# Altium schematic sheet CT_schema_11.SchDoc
size 741 x 377 mm
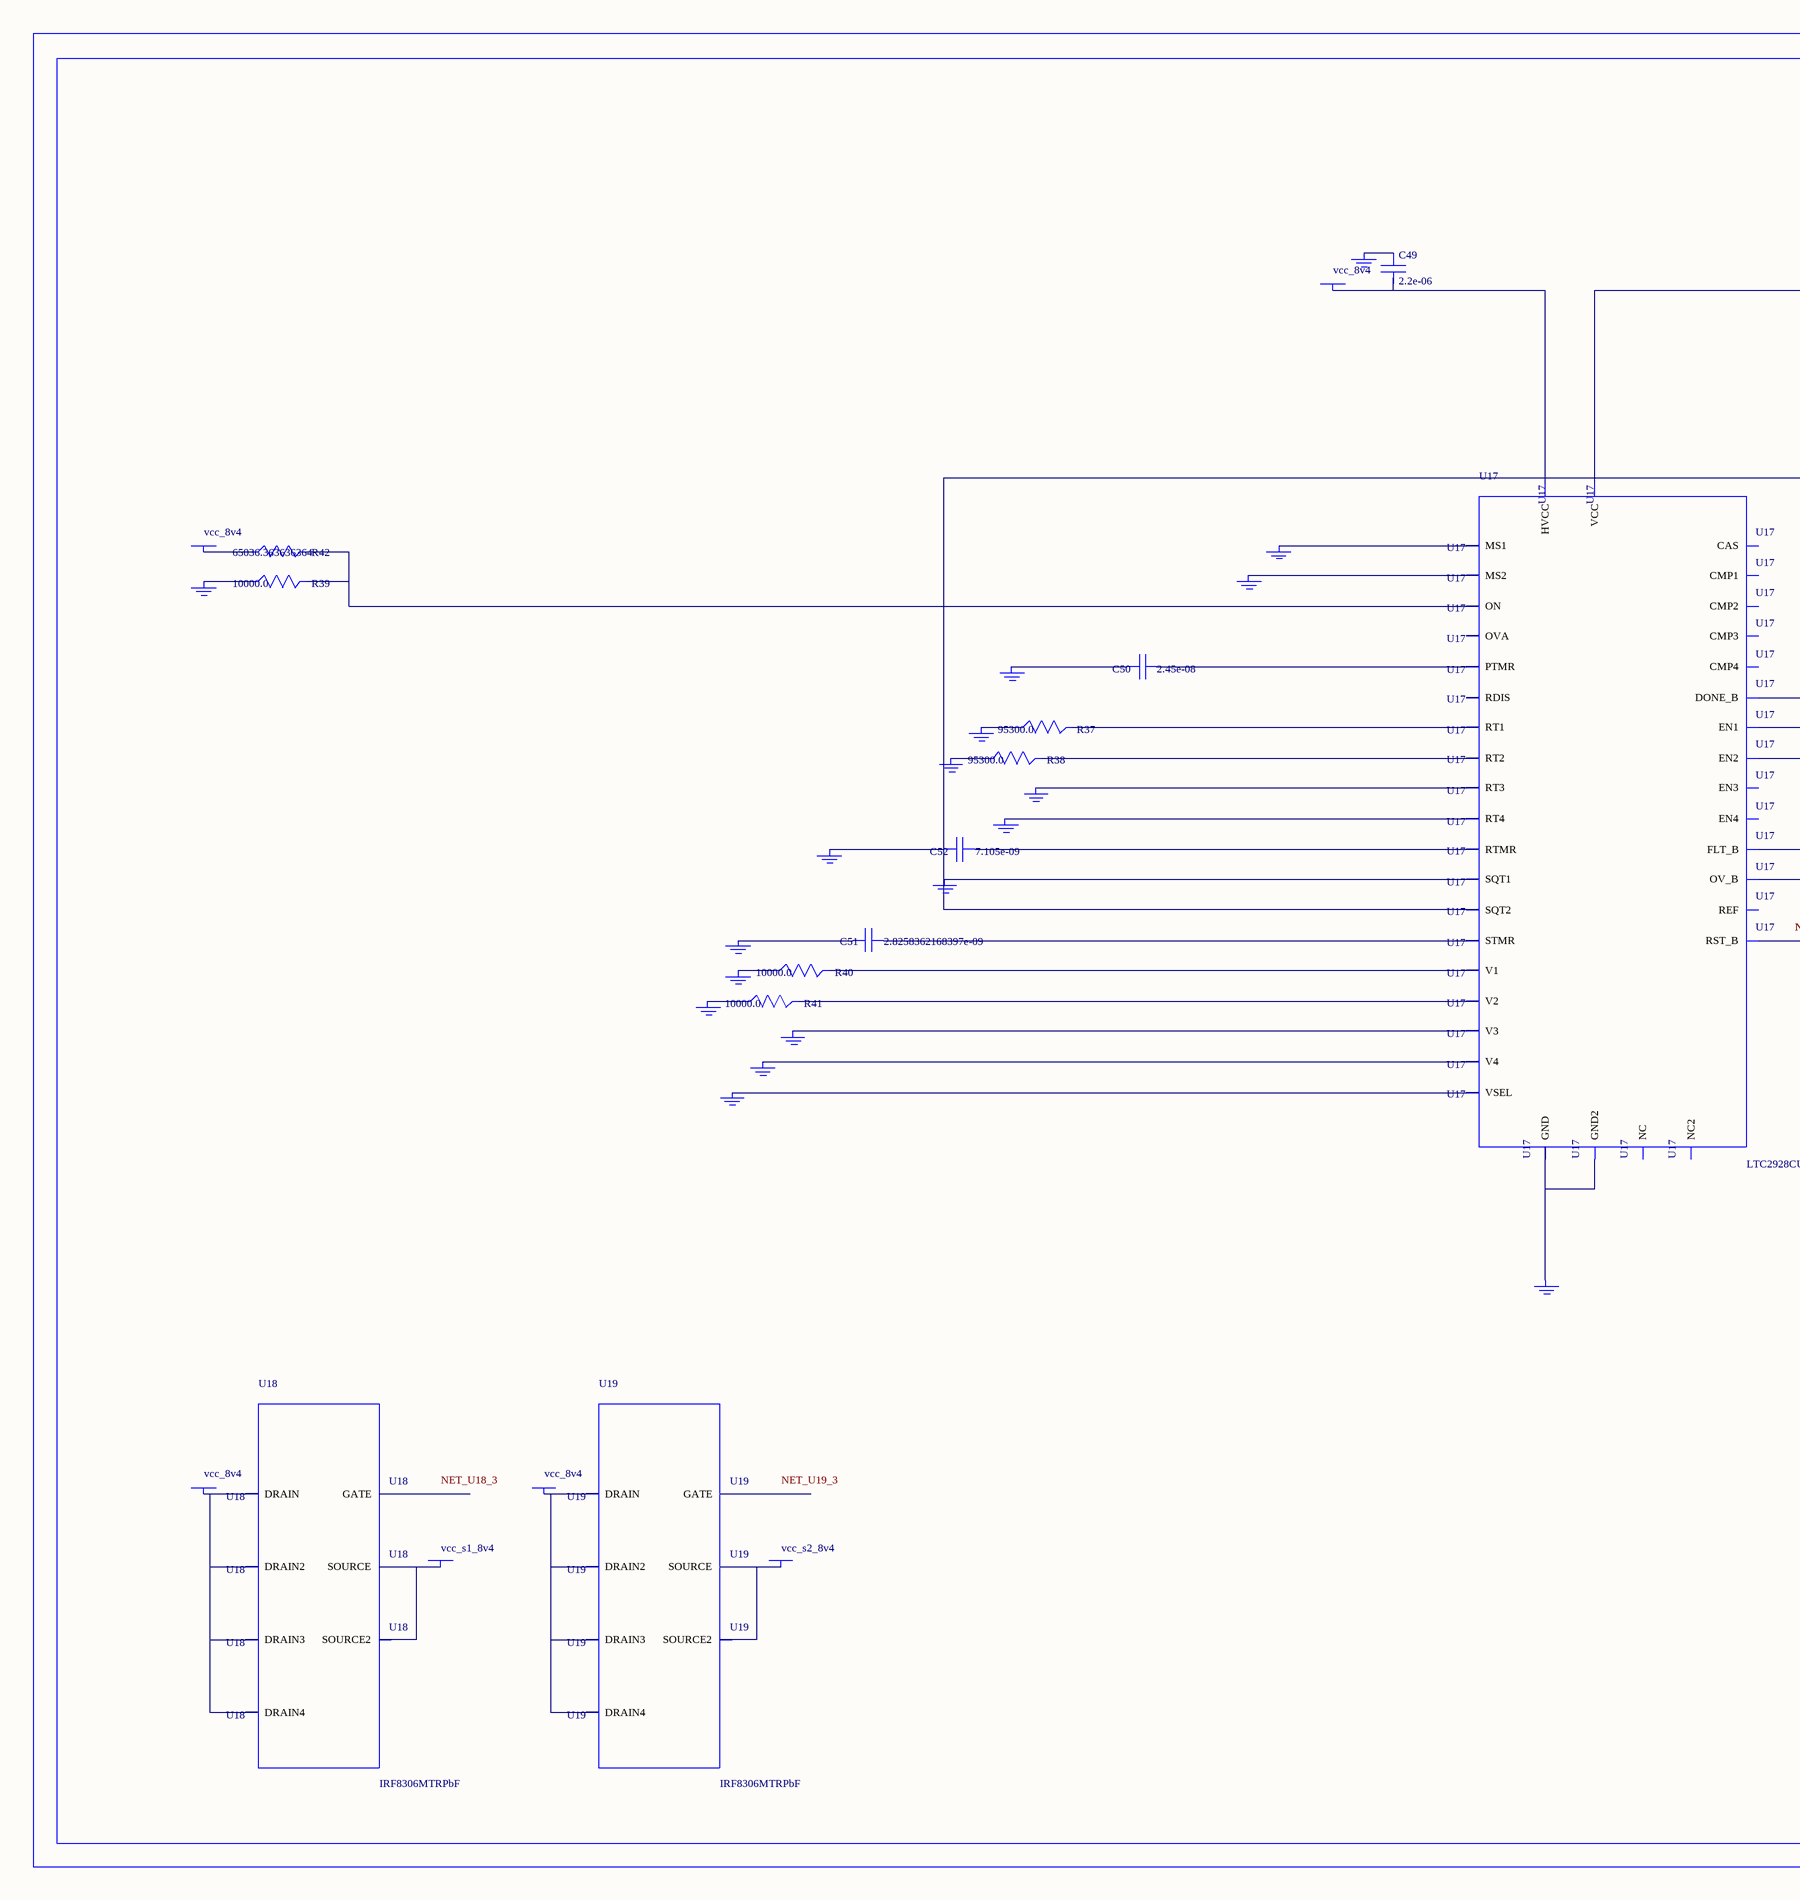
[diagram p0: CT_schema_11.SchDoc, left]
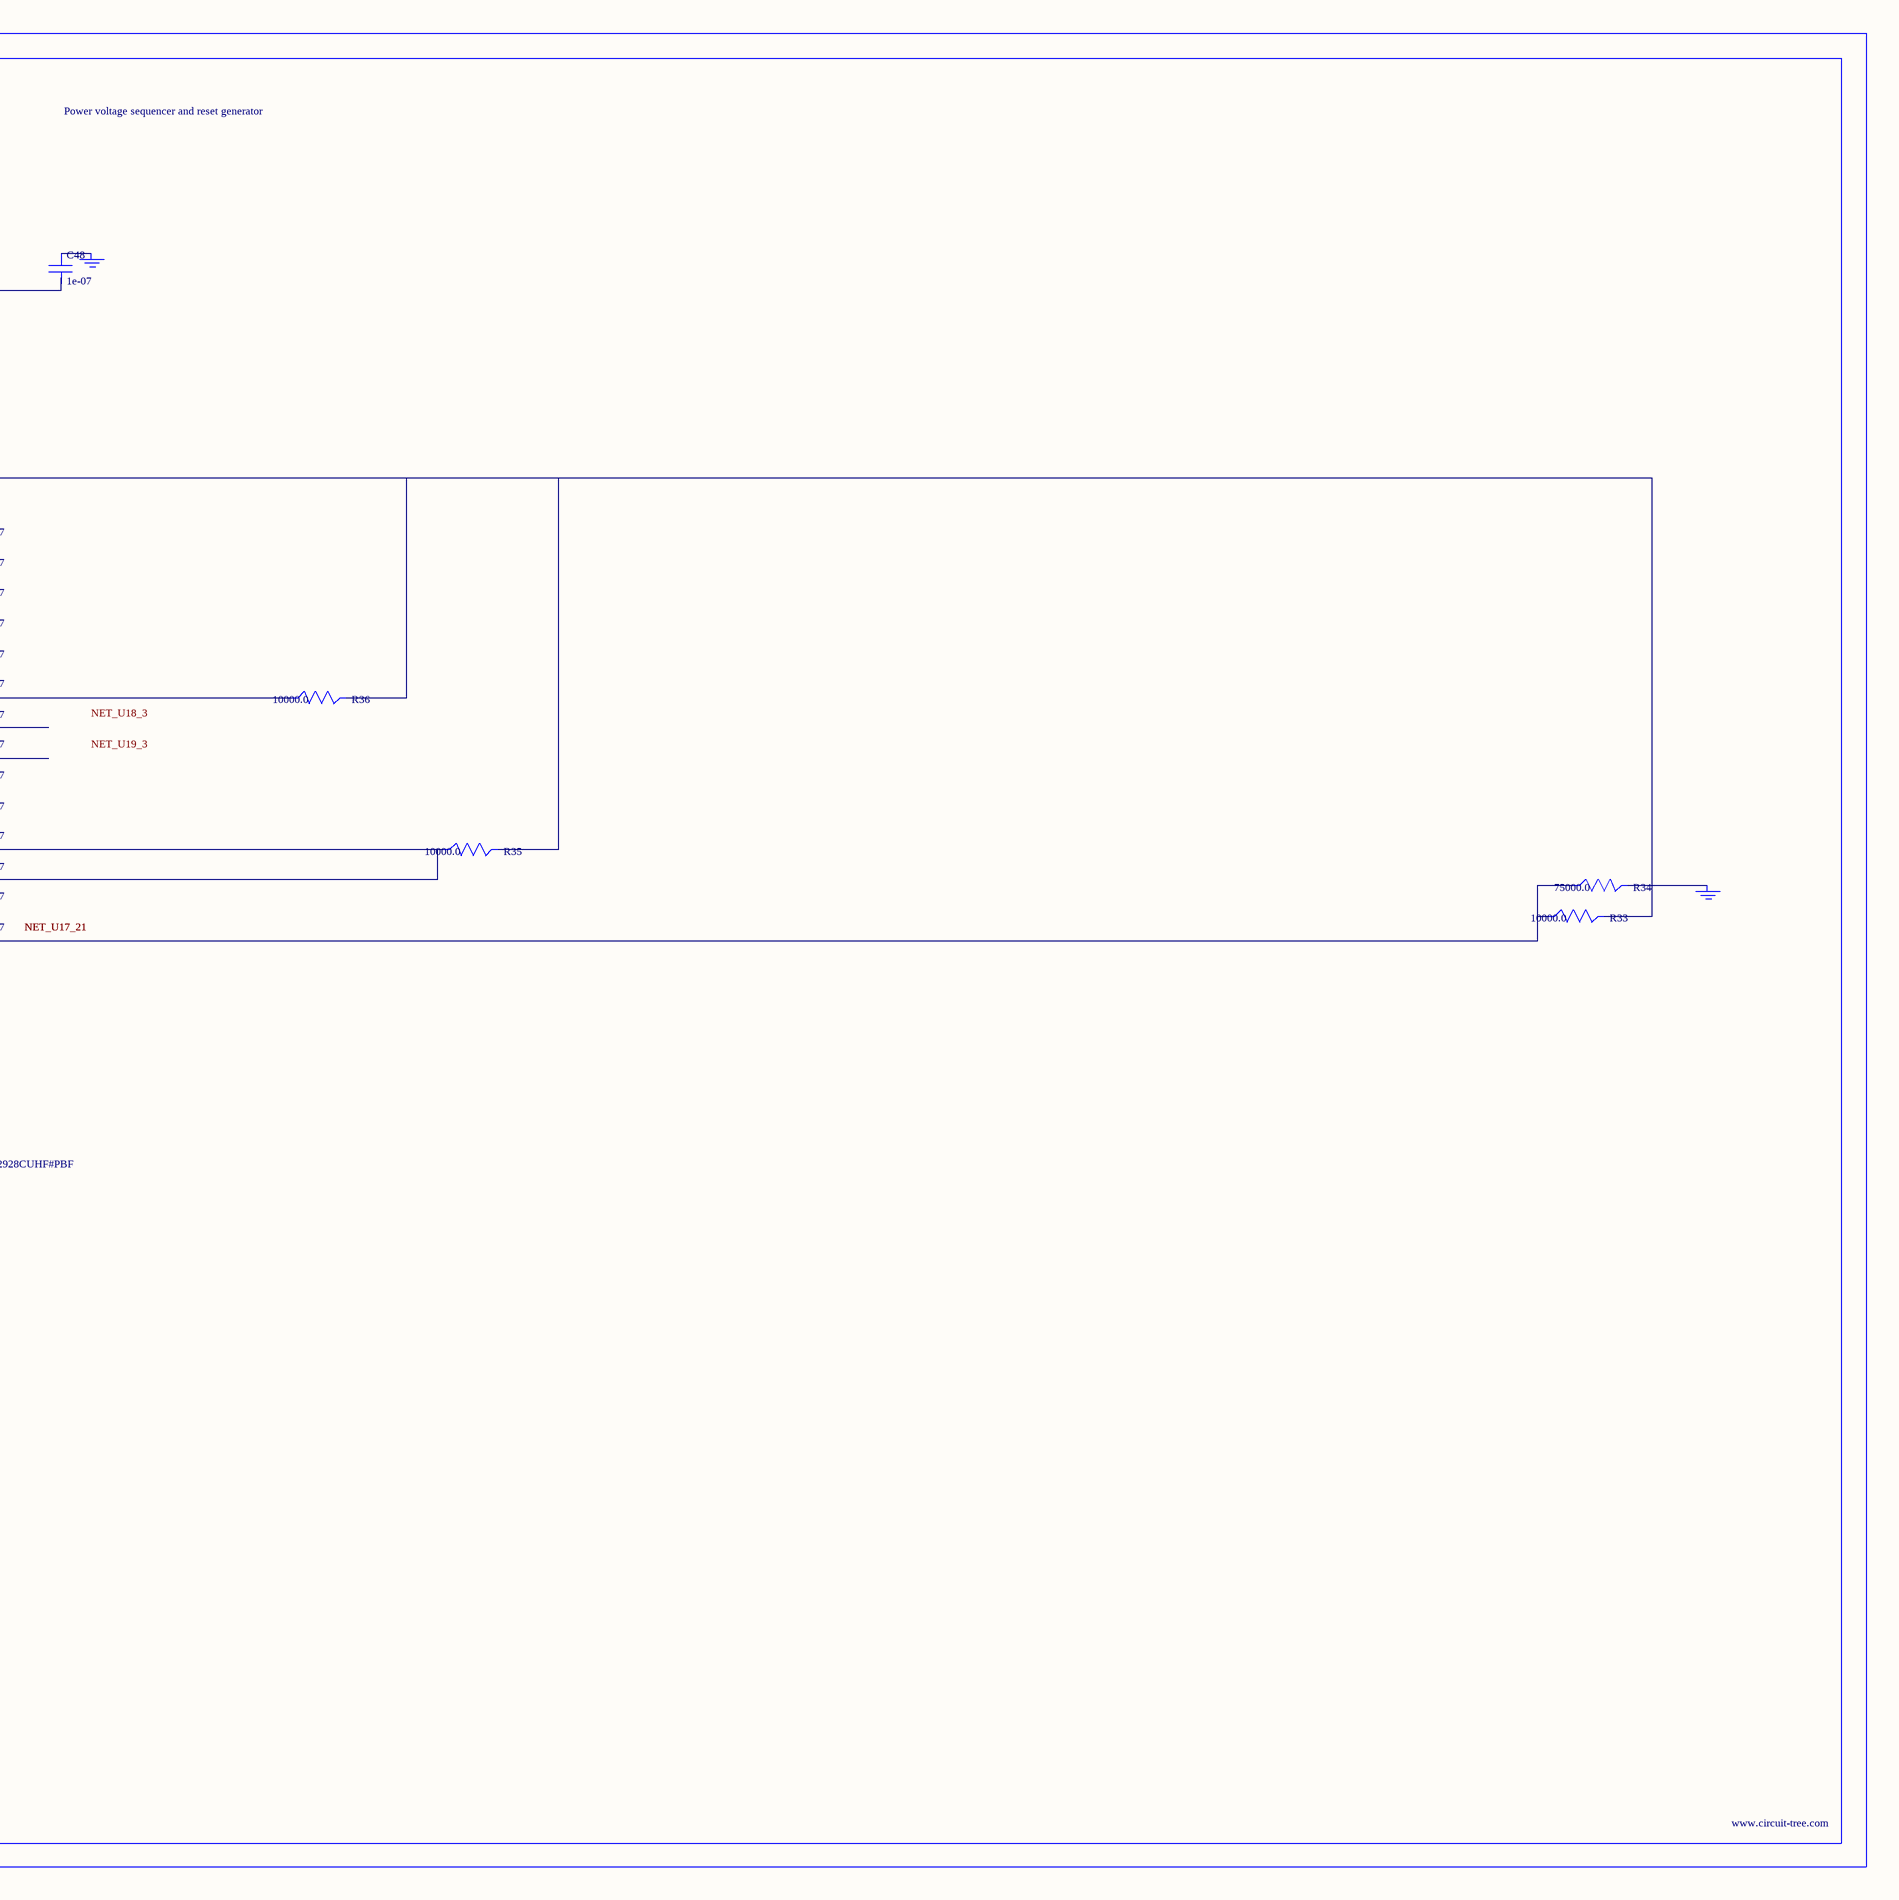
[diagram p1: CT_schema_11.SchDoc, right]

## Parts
BORDER10  (no value)
C48  1e-07  [C0402]
C49  2.2e-06  [C0603]
C50  2.45e-08  [R0603]
C51  2.8258362168397e-09  [R0603]
C52  7.105e-09  [R0603]
GND_INSTANCE_10_0  (no value)
GND_INSTANCE_10_1  (no value)
GND_INSTANCE_10_2  (no value)
GND_INSTANCE_10_3  (no value)
GND_INSTANCE_10_4  (no value)
GND_INSTANCE_10_5  (no value)
GND_INSTANCE_10_6  (no value)
GND_INSTANCE_10_7  (no value)
GND_INSTANCE_10_8  (no value)
GND_INSTANCE_10_9  (no value)
GND_INSTANCE_10_10  (no value)
GND_INSTANCE_10_11  (no value)
GND_INSTANCE_10_12  (no value)
GND_INSTANCE_10_13  (no value)
GND_INSTANCE_10_14  (no value)
GND_INSTANCE_10_15  (no value)
GND_INSTANCE_10_16  (no value)
GND_INSTANCE_10_17  (no value)
GND_INSTANCE_10_18  (no value)
GND_INSTANCE_10_19  (no value)
POWER_INSTANCE_10_0  vcc_8v4
POWER_INSTANCE_10_1  vcc_8v4
POWER_INSTANCE_10_2  vcc_8v4
POWER_INSTANCE_10_3  vcc_s1_8v4
POWER_INSTANCE_10_4  vcc_8v4
POWER_INSTANCE_10_5  vcc_s2_8v4
R33  10000.0  [R0603]
R34  75000.0  [R0603]
R35  10000.0  [R0603]
R36  10000.0  [R0603]
R37  95300.0  [R0603]
R38  95300.0  [R0603]
R39  10000.0  [R0603]
R40  10000.0  [R0603]
R41  10000.0  [R0603]
R42  65036.363636364  [R0603]
U17  LTC2928CUHF#PBF  [QFN-38_UHF]
U18  IRF8306MTRPbF  [IRF8306MTRPBF]
U19  IRF8306MTRPbF  [IRF8306MTRPBF]

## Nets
NetC48_1: C48.1 GND_INSTANCE_10_10.0(GND)
NetC48_2: C48.2 C52.2 GND_INSTANCE_10_5.0(GND) GND_INSTANCE_10_15.0(GND) R33.2 R35.2 R36.2 U17.10(SQT1) U17.11(SQT2) U17.22(VCC)
NetC49_1: C49.1 GND_INSTANCE_10_11.0(GND)
NetC49_2: C49.2 POWER_INSTANCE_10_1.0(PWR) U17.23(HVCC)
NetC50_1: C50.1 U17.27(PTMR)
NetC50_2: C50.2 GND_INSTANCE_10_14.0(GND)
NetC51_1: C51.1 U17.26(STMR)
NetC51_2: C51.2 GND_INSTANCE_10_13.0(GND)
NetC52_1: C52.1 U17.28(RTMR)
NetGND_INSTANCE_10_0_0: GND_INSTANCE_10_0.0(GND) R40.1
NetGND_INSTANCE_10_1_0: GND_INSTANCE_10_1.0(GND) R37.1
NetGND_INSTANCE_10_2_0: GND_INSTANCE_10_2.0(GND) R38.1
NetGND_INSTANCE_10_3_0: GND_INSTANCE_10_3.0(GND) U17.8(RT3)
NetGND_INSTANCE_10_4_0: GND_INSTANCE_10_4.0(GND) U17.9(RT4)
NetGND_INSTANCE_10_6_0: GND_INSTANCE_10_6.0(GND) U17.12(MS1)
NetGND_INSTANCE_10_7_0: GND_INSTANCE_10_7.0(GND) U17.13(MS2)
NetGND_INSTANCE_10_8_0: GND_INSTANCE_10_8.0(GND) R39.1
NetGND_INSTANCE_10_9_0: GND_INSTANCE_10_9.0(GND) R34.2
NetGND_INSTANCE_10_12_0: GND_INSTANCE_10_12.0(GND) U17.25(VSEL)
NetGND_INSTANCE_10_16_0: GND_INSTANCE_10_16.0(GND) U17.30(V4)
NetGND_INSTANCE_10_17_0: GND_INSTANCE_10_17.0(GND) U17.32(V3)
NetGND_INSTANCE_10_18_0: GND_INSTANCE_10_18.0(GND) R41.1
NetGND_INSTANCE_10_19_0: GND_INSTANCE_10_19.0(GND) U17.24(GND) U17.39(GND2)
NetPOWER_INSTANCE_10_0_0: POWER_INSTANCE_10_0.0(PWR) R42.1
NetPOWER_INSTANCE_10_2_0: POWER_INSTANCE_10_2.0(PWR) U18.1(DRAIN) U18.2(DRAIN2) U18.6(DRAIN3) U18.7(DRAIN4)
NetPOWER_INSTANCE_10_3_0: POWER_INSTANCE_10_3.0(PWR) U18.4(SOURCE) U18.5(SOURCE2)
NetPOWER_INSTANCE_10_4_0: POWER_INSTANCE_10_4.0(PWR) U19.1(DRAIN) U19.2(DRAIN2) U19.6(DRAIN3) U19.7(DRAIN4)
NetPOWER_INSTANCE_10_5_0: POWER_INSTANCE_10_5.0(PWR) U19.4(SOURCE) U19.5(SOURCE2)
NetR33_1: R33.1 R34.1 U17.21(RST_B)
NetR35_1: R35.1 U17.19(FLT_B) U17.20(OV_B)
NetR36_1: R36.1 U17.18(DONE_B)
NetR37_2: R37.2 U17.6(RT1)
NetR38_2: R38.2 U17.7(RT2)
NetR39_2: R39.2 R42.2 U17.16(ON)
NetR40_2: R40.2 U17.3(V1)
NetR41_2: R41.2 U17.38(V2)

Not connected (* = marked no-connect by the designer): U17 1(OVA) 2(EN1) 4(NC) 5(REF) 14(RDIS) 15(CAS) 17(NC2) 29(EN4) 31(EN3) 33(CMP3) 34(CMP4) 35(CMP1) 36(CMP2) 37(EN2); U18 3(GATE); U19 3(GATE)

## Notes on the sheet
- Labels drawn without touching a wire or pin: NET_U18_3, NET_U19_3

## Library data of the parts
BORDER10 = BORDER_PAGE10
C48 = C0402C104K3RACTU
C49 = GRM188R61H225KE1115D
C50 = C50
C51 = C51
C52 = C52
GND_INSTANCE_10_0-GND_INSTANCE_10_19 = GND
POWER_INSTANCE_10_0-POWER_INSTANCE_10_5 = PWR
R33 R35 R36 R39-R41 = RC0603JR-0710KL
R34 = RC0603JR-0775KL
R37 R38 = RC0603FR-0795K3L
R42 = R42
